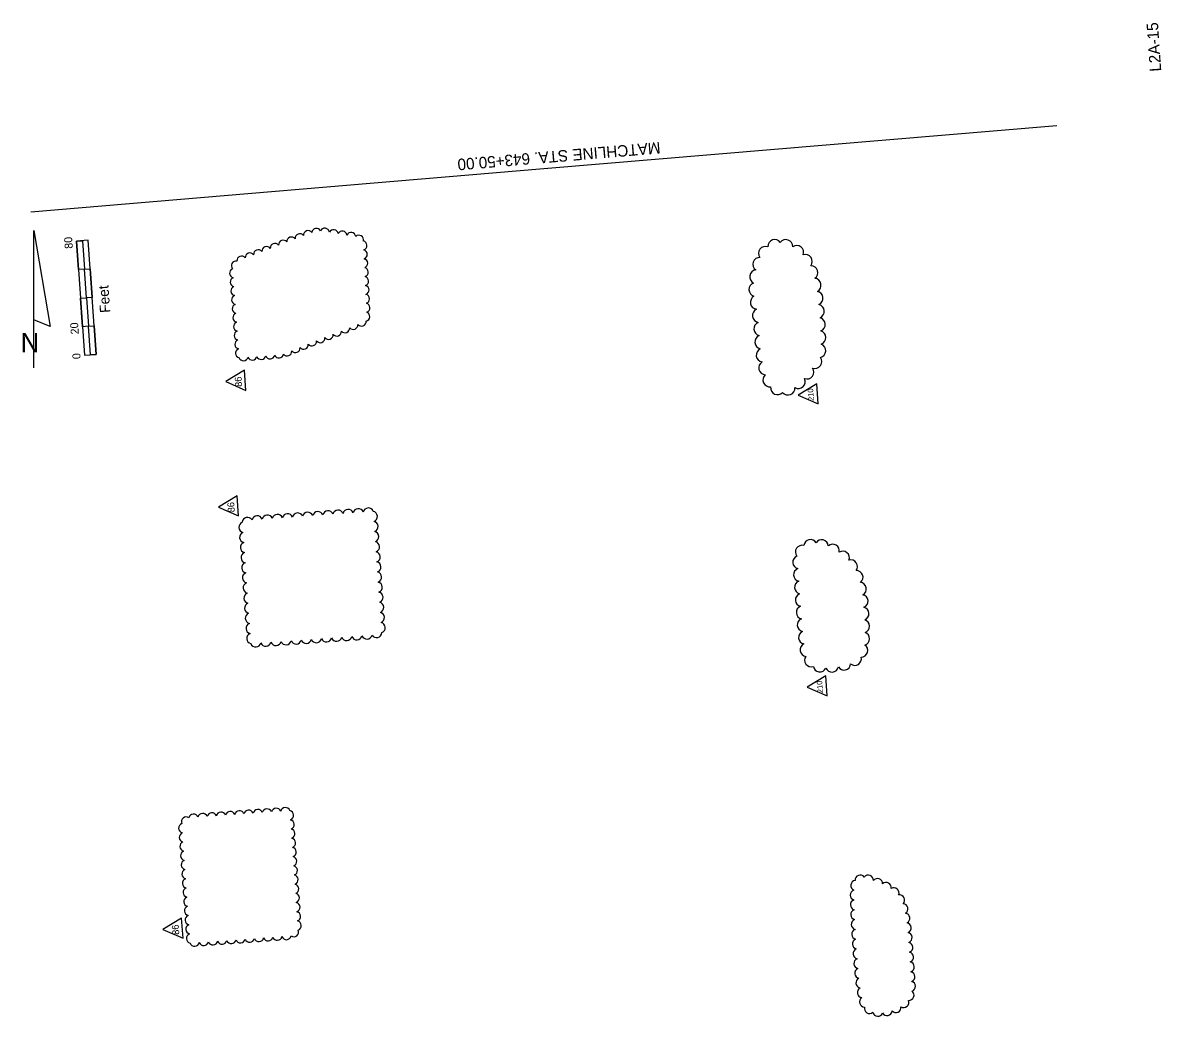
# Model space of a CAD drawing. Extents: x 928662 to 929564, y 639038 to 640295.
# Drawn here: x 928662 to 929458, y 639600 to 640295 of the extents above; entities that cross this region are included whole.
import ezdxf

# ---------------------------------------------------------------- set-up
doc = ezdxf.new("R2010")
doc.units = 0
for name, color, linetype in [('Cloud_dp', 7, 'Continuous'), ('MatchLines_dp', 7, 'Continuous'), ('NorthArw_dp', 7, 'Continuous'), ('Scale_dp', 7, 'Continuous'), ('TextShtNo', 7, 'Continuous')]:
    doc.layers.add(name, color=color, linetype=linetype)

msp = doc.modelspace()

# ---------------------------------------------------------------- linework, layer by layer
at = {"layer": 'Cloud_dp'}
for points in [[(928803.74, 640043.78), (928817.76, 640037.7), (928816.77, 640051.75)], [(929204.11, 640034.36), (929218.13, 640028.28), (929217.14, 640042.33)], [(928798.6, 639956.07), (928812.63, 639949.99), (928811.64, 639964.04)], [(929210.42, 639830.12), (929224.44, 639824.04), (929223.45, 639838.09)], [(928759.76, 639660.72), (928773.79, 639654.64), (928772.8, 639668.69)]]:
    msp.add_lwpolyline(points, close=True, dxfattribs=at)
for centre, radius, start, end in [((928861.31, 640146.07), 3.27, 38.44496, 183.44496), ((928867.11, 640147.7), 3.27, 27.90022, 172.90022), ((928872.92, 640147.77), 3.27, 8.41691, 153.41691), ((928879.07, 640146.78), 3.27, 8.41691, 153.41691), ((928885.22, 640145.8), 3.27, 8.41691, 153.41691), ((928838.04, 640137.16), 3.27, 38.44496, 183.44496), ((928843.86, 640139.39), 3.27, 38.44496, 183.44496), ((928849.67, 640141.62), 3.27, 38.44496, 183.44496), ((928855.49, 640143.84), 3.27, 38.44496, 183.44496), ((928891.37, 640144.81), 3.27, 8.41691, 153.41691), ((928896.78, 640142.85), 3.27, 346.702, 131.702), ((928899.13, 640138.94), 3.27, 290.27845, 75.27845), ((929187.65, 640138.22), 4.85, 36.45605, 181.45605), ((929195.45, 640138.21), 4.85, 358.40857, 143.40857), ((928820.58, 640130.48), 3.27, 38.44496, 183.44496), ((928826.4, 640132.71), 3.27, 38.44496, 183.44496), ((928832.22, 640134.94), 3.27, 38.44496, 183.44496), ((928899.43, 640132.72), 3.27, 290.27845, 75.27845), ((929181.23, 640133.5), 4.85, 71.25472, 216.25472), ((929203.04, 640134.07), 4.85, 339.41877, 124.41877), ((929209.08, 640127.75), 4.85, 322.92208, 107.92208), ((928810.84, 640124.86), 3.27, 78.21602, 223.21602), ((928814.76, 640128.25), 3.27, 38.44496, 183.44496), ((928899.73, 640126.5), 3.27, 290.27845, 75.27845), ((929177.2, 640125.78), 4.85, 88.62539, 233.62539), ((929212.97, 640119.97), 4.85, 305.19249, 90.19249), ((928809.66, 640119.59), 3.27, 111.71689, 256.71689), ((928900.03, 640120.28), 3.27, 290.27845, 75.27845), ((928900.33, 640114.05), 3.27, 290.27845, 75.27845), ((929175.04, 640117.07), 4.85, 98.42028, 243.42028), ((928810.12, 640113.38), 3.27, 111.71689, 256.71689), ((928810.58, 640107.16), 3.27, 111.71689, 256.71689), ((928900.64, 640107.83), 3.27, 290.27845, 75.27845), ((929174.46, 640108.14), 4.85, 109.16671, 254.16671), ((929215.19, 640111.18), 4.85, 298.16543, 83.16543), ((928811.04, 640100.95), 3.27, 111.71689, 256.71689), ((928900.94, 640101.61), 3.27, 290.27845, 75.27845), ((929175.44, 640099.2), 4.85, 118.43265, 263.43265), ((929216.59, 640102.13), 4.85, 294.39112, 79.39112), ((928811.5, 640094.74), 3.27, 111.71689, 256.71689), ((928901.24, 640095.38), 3.27, 290.27845, 75.27845), ((929176.96, 640089.99), 4.85, 115.30895, 260.30895), ((929217.5, 640092.98), 4.85, 292.00794, 77.00794), ((928811.95, 640088.52), 3.27, 111.71689, 256.71689), ((928812.41, 640082.31), 3.27, 111.71689, 256.71689), ((928898.67, 640085.86), 3.27, 219.29844, 4.29844), ((928901.17, 640089.28), 3.27, 283.41856, 68.41856), ((929177.93, 640080.69), 4.85, 111.51956, 256.51956), ((929218.13, 640083.77), 4.85, 290.76114, 75.76114), ((928812.87, 640076.1), 3.27, 111.71689, 256.71689), ((928875.53, 640076.61), 3.27, 219.29844, 4.29844), ((928881.32, 640078.92), 3.27, 219.29844, 4.29844), ((928887.1, 640081.23), 3.27, 219.29844, 4.29844), ((928892.89, 640083.55), 3.27, 219.29844, 4.29844), ((929218.52, 640074.56), 4.85, 289.15603, 74.15603), ((928813.33, 640069.88), 3.27, 111.71689, 256.71689), ((928858.18, 640069.67), 3.27, 219.29844, 4.29844), ((928863.96, 640071.98), 3.27, 219.29844, 4.29844), ((928869.75, 640074.29), 3.27, 219.29844, 4.29844), ((929178.58, 640071.46), 4.85, 111.62555, 256.62555), ((929218.44, 640065.42), 4.86, 284.84092, 69.84092), ((928813.79, 640063.67), 3.27, 111.71689, 256.71689), ((928816.07, 640061.69), 3.27, 201.51956, 346.51956), ((928822.29, 640062.13), 3.27, 201.51956, 346.51956), ((928828.5, 640062.56), 3.27, 201.51956, 346.51956), ((928834.72, 640063), 3.27, 201.51956, 346.51956), ((928840.87, 640063.58), 3.27, 204.25712, 349.25712), ((928846.61, 640065.04), 3.27, 219.29844, 4.29844), ((928852.39, 640067.35), 3.27, 219.29844, 4.29844), ((929179.56, 640062.36), 4.85, 115.59926, 260.59926), ((929181.32, 640053.44), 4.85, 121.70192, 266.70192), ((929210.2, 640050.49), 4.85, 250.40847, 35.40847), ((929215.75, 640057.89), 4.85, 250.82888, 35.82888), ((929184.24, 640044.94), 4.85, 131.22944, 276.22944), ((929204.19, 640043.84), 4.85, 240.39595, 25.39595), ((929189.58, 640039.5), 4.85, 172.73368, 317.73368), ((929196.95, 640039.29), 4.85, 218.89596, 3.89596), ((928825.71, 639946.29), 3.71, 21.51956, 166.51956), ((928832.78, 639946.78), 3.71, 21.51956, 166.51956), ((928839.84, 639947.28), 3.71, 21.51956, 166.51956), ((928846.91, 639947.78), 3.71, 21.51956, 166.51956), ((928853.98, 639948.27), 3.71, 21.51956, 166.51956), ((928861.04, 639948.77), 3.71, 21.51956, 166.51956), ((928868.11, 639949.27), 3.71, 21.51956, 166.51956), ((928875.17, 639949.76), 3.71, 21.51956, 166.51956), ((928882.24, 639950.26), 3.71, 21.51956, 166.51956), ((928889.31, 639950.76), 3.71, 21.51956, 166.51956), ((928896.37, 639951.25), 3.71, 21.51956, 166.51956), ((928903.44, 639951.75), 3.71, 21.51956, 166.51956), ((928906.03, 639949.5), 3.71, 291.51956, 76.51956), ((928816.6, 639941.99), 3.71, 111.51956, 256.51956), ((928818.94, 639945.22), 3.71, 31.48234, 176.48234), ((928906.52, 639942.43), 3.71, 291.51956, 76.51956), ((928817.09, 639934.92), 3.71, 111.51956, 256.51956), ((928907.02, 639935.37), 3.71, 291.51956, 76.51956), ((929212.58, 639928.78), 4.61, 29.64625, 174.64625), ((928817.59, 639927.86), 3.71, 111.51956, 256.51956), ((928907.52, 639928.3), 3.71, 291.51956, 76.51956), ((929206.75, 639924.76), 4.61, 74.42336, 219.42336), ((929220.54, 639928.67), 4.61, 3.80823, 148.80823), ((929228.22, 639925.53), 4.61, 346.72291, 131.72291), ((928818.08, 639920.79), 3.71, 111.51956, 256.51956), ((928908.01, 639921.24), 3.71, 291.51956, 76.51956), ((928908.51, 639914.17), 3.71, 291.51956, 76.51956), ((929204.88, 639917.54), 4.61, 111.51956, 256.51956), ((929235.25, 639920.62), 4.61, 338.37511, 123.37511), ((929240.91, 639914.51), 4.61, 322.33613, 107.33613), ((928818.58, 639913.72), 3.71, 111.51956, 256.51956), ((928819.08, 639906.66), 3.71, 111.51956, 256.51956), ((928909.01, 639907.1), 3.71, 291.51956, 76.51956), ((929205.49, 639908.76), 4.61, 111.51956, 256.51956), ((929244.8, 639907.08), 4.61, 307.85682, 92.85682), ((928819.57, 639899.59), 3.71, 111.51956, 256.51956), ((928909.5, 639900.04), 3.71, 291.51956, 76.51956), ((929206.11, 639899.98), 4.61, 111.51956, 256.51956), ((929247.1, 639898.85), 4.61, 298.46446, 83.46446), ((928820.07, 639892.53), 3.71, 111.51956, 256.51956), ((928910, 639892.97), 3.71, 291.51956, 76.51956), ((929206.73, 639891.2), 4.61, 111.51956, 256.51956), ((929248.3, 639890.29), 4.61, 292.48809, 77.48809), ((928820.57, 639885.46), 3.71, 111.51956, 256.51956), ((928910.49, 639885.91), 3.71, 291.51956, 76.51956), ((929207.36, 639882.42), 4.61, 111.67462, 256.67462), ((929248.93, 639881.56), 4.61, 290.73286, 75.73286), ((928821.06, 639878.39), 3.71, 111.51956, 256.51956), ((928910.99, 639878.84), 3.71, 291.51956, 76.51956), ((929208.05, 639873.66), 4.61, 112.42543, 257.42543), ((928821.56, 639871.33), 3.71, 111.51956, 256.51956), ((928911.49, 639871.77), 3.71, 291.51956, 76.51956), ((929249.32, 639872.8), 4.61, 289.3615, 74.3615), ((928822.06, 639864.26), 3.71, 111.51956, 256.51956), ((928838.78, 639863.01), 3.71, 201.51956, 346.51956), ((928845.84, 639863.5), 3.71, 201.51956, 346.51956), ((928852.91, 639864), 3.71, 201.51956, 346.51956), ((928859.98, 639864.5), 3.71, 201.51956, 346.51956), ((928867.04, 639864.99), 3.71, 201.51956, 346.51956), ((928874.11, 639865.49), 3.71, 201.51956, 346.51956), ((928881.17, 639865.99), 3.71, 201.51956, 346.51956), ((928888.24, 639866.48), 3.71, 201.51956, 346.51956), ((928895.31, 639866.98), 3.71, 201.51956, 346.51956), ((928902.37, 639867.48), 3.71, 201.51956, 346.51956), ((928909.15, 639868.55), 3.71, 211.48234, 356.48234), ((929208.91, 639864.93), 4.61, 113.72906, 258.72906), ((929249.4, 639864.06), 4.61, 286.63121, 71.63121), ((928824.65, 639862.01), 3.71, 201.51956, 346.51956), ((928831.71, 639862.51), 3.71, 201.51956, 346.51956), ((929210.08, 639856.29), 4.62, 116.74711, 261.74711), ((929248.09, 639855.85), 4.61, 270.26997, 55.26997), ((929213.17, 639849.03), 4.61, 144.35853, 289.35853), ((929236.13, 639846.78), 4.61, 210.71872, 355.71872), ((929243.66, 639850), 4.61, 230.55531, 15.55531), ((929219.25, 639845.44), 4.61, 189.46011, 334.46011), ((929227.63, 639845.31), 4.61, 203.84085, 348.84085), ((928793.98, 639739.03), 3.38, 21.51956, 166.51956), ((928800.4, 639739.49), 3.38, 21.51956, 166.51956), ((928806.83, 639739.94), 3.38, 21.51956, 166.51956), ((928813.26, 639740.39), 3.38, 21.51956, 166.51956), ((928819.68, 639740.84), 3.38, 21.51956, 166.51956), ((928826.11, 639741.29), 3.38, 21.51956, 166.51956), ((928832.54, 639741.74), 3.38, 21.51956, 166.51956), ((928838.96, 639742.2), 3.38, 21.51956, 166.51956), ((928845.39, 639742.65), 3.38, 21.51956, 166.51956), ((928847.74, 639740.6), 3.38, 291.51956, 76.51956), ((928774.11, 639731.69), 3.38, 111.51956, 256.51956), ((928776, 639736.09), 3.38, 56.95108, 201.95108), ((928781.12, 639738.13), 3.38, 21.51956, 166.51956), ((928787.55, 639738.58), 3.38, 21.51956, 166.51956), ((928848.2, 639734.18), 3.38, 291.51956, 76.51956), ((928774.56, 639725.26), 3.38, 111.51956, 256.51956), ((928848.65, 639727.75), 3.38, 291.51956, 76.51956), ((928775.01, 639718.83), 3.38, 111.51956, 256.51956), ((928849.1, 639721.32), 3.38, 291.51956, 76.51956), ((928775.46, 639712.41), 3.38, 111.51956, 256.51956), ((928849.55, 639714.9), 3.38, 291.51956, 76.51956), ((928850, 639708.47), 3.38, 291.51956, 76.51956), ((928775.91, 639705.98), 3.38, 111.51956, 256.51956), ((928776.37, 639699.55), 3.38, 111.51956, 256.51956), ((928850.45, 639702.04), 3.38, 291.51956, 76.51956), ((928776.82, 639693.13), 3.38, 111.51956, 256.51956), ((928850.91, 639695.62), 3.38, 291.51956, 76.51956), ((929244.51, 639691.56), 3.6, 101.00121, 246.00121), ((929247.41, 639695.27), 3.59, 37.91777, 182.91777), ((929253.07, 639695.25), 3.59, 356.85595, 141.85595), ((929259.51, 639692.87), 3.59, 357.42093, 142.42093), ((928777.27, 639686.7), 3.38, 111.51956, 256.51956), ((928851.36, 639689.19), 3.38, 291.51956, 76.51956), ((929244.1, 639684.83), 3.59, 107.09663, 252.09663), ((929265.6, 639690.12), 3.59, 349.0536, 134.0536), ((929271, 639686.37), 3.59, 336.44541, 121.44541), ((928777.72, 639680.27), 3.38, 111.51956, 256.51956), ((928851.81, 639682.76), 3.38, 291.51956, 76.51956), ((928852.26, 639676.34), 3.38, 291.51956, 76.51956), ((929244.16, 639678.01), 3.59, 108.9267, 253.9267), ((929274.9, 639681.39), 3.59, 314.78184, 99.78184), ((929277.22, 639675.25), 3.59, 301.60517, 86.60517), ((928778.17, 639673.85), 3.38, 111.51956, 256.51956), ((928852.71, 639669.91), 3.38, 291.51956, 76.51956), ((929244.39, 639671.18), 3.59, 109.91714, 254.91714), ((929278.58, 639668.64), 3.59, 296.63128, 81.63128), ((928778.62, 639667.42), 3.38, 111.51956, 256.51956), ((928779.08, 639660.99), 3.38, 111.51956, 256.51956), ((928853.16, 639663.48), 3.38, 291.51956, 76.51956), ((929244.72, 639664.35), 3.59, 110.56232, 255.56232), ((929279.5, 639661.9), 3.59, 293.86107, 78.86107), ((928779.53, 639654.57), 3.38, 111.51956, 256.51956), ((928826.87, 639655.68), 3.38, 201.51956, 346.51956), ((928833.29, 639656.13), 3.38, 201.51956, 346.51956), ((928839.72, 639656.59), 3.38, 201.51956, 346.51956), ((928846.15, 639657.04), 3.38, 201.51956, 346.51956), ((928851.27, 639659.08), 3.38, 236.95108, 21.95108), ((929245.11, 639657.51), 3.59, 111.02556, 256.02556), ((929280.15, 639655.11), 3.59, 292.05713, 77.05713), ((928781.88, 639652.52), 3.38, 201.51956, 346.51956), ((928788.31, 639652.97), 3.38, 201.51956, 346.51956), ((928794.73, 639653.43), 3.38, 201.51956, 346.51956), ((928801.16, 639653.88), 3.38, 201.51956, 346.51956), ((928807.59, 639654.33), 3.38, 201.51956, 346.51956), ((928814.01, 639654.78), 3.38, 201.51956, 346.51956), ((928820.44, 639655.23), 3.38, 201.51956, 346.51956), ((929245.56, 639650.68), 3.59, 111.39485, 256.39485), ((929246.05, 639643.85), 3.59, 111.87739, 256.87739), ((929280.66, 639648.28), 3.59, 291.51956, 76.51956), ((929246.61, 639637.03), 3.59, 112.52713, 257.52713), ((929281.14, 639641.44), 3.59, 291.51956, 76.51956), ((929247.26, 639630.22), 3.59, 113.42025, 258.42025), ((929281.62, 639634.6), 3.59, 291.51956, 76.51956), ((929282.1, 639627.77), 3.59, 291.51956, 76.51956), ((929248.05, 639623.43), 3.59, 114.76058, 259.76058), ((929282.52, 639620.94), 3.59, 290.40029, 75.40029), ((929249.05, 639616.7), 3.59, 117.11892, 262.11892), ((929281.49, 639614.8), 3.59, 265.64843, 50.64843), ((929250.53, 639610.14), 3.59, 123.37709, 268.37709), ((929277.9, 639609.84), 3.59, 237.46395, 22.46395), ((929253.91, 639605.63), 3.59, 165.30878, 310.30878), ((929259.72, 639603.75), 3.59, 193.86536, 338.86536), ((929266.22, 639604.2), 3.59, 208.98392, 353.98392), ((929272.41, 639606.29), 3.59, 223.32698, 8.32698)]:
    msp.add_arc(centre, radius, start, end, dxfattribs=at)
at = {"layer": 'MatchLines_dp'}
msp.add_lwpolyline([(929384.91, 640222.63), (929026.17, 640192.5), (928667.43, 640162.36)], dxfattribs=at)
at = {"layer": 'NorthArw_dp'}
msp.add_line((928669.37, 640053.44), (928669.37, 640149.44), dxfattribs=at)
msp.add_lwpolyline([(928669.37, 640087.04), (928669.37, 640149.44), (928680.89, 640082.24)], close=True, dxfattribs=at)
at = {"layer": 'Scale_dp'}
for p, q in [((928707.38, 640142.6), (928699.4, 640142.04)), ((928699.4, 640142.04), (928705, 640062.24)), ((928712.98, 640062.8), (928707.38, 640142.6)), ((928705, 640062.24), (928712.98, 640062.8))]:
    msp.add_line(p, q, dxfattribs=at)
for points in [[(928704.79, 640122.37), (928700.8, 640122.09), (928699.4, 640142.04), (928703.39, 640142.32)], [(928710.18, 640102.7), (928706.19, 640102.42), (928704.79, 640122.37), (928708.78, 640122.65)], [(928707.59, 640082.47), (928703.6, 640082.19), (928702.2, 640102.14), (928706.19, 640102.42)], [(928712.98, 640062.8), (928708.99, 640062.52), (928707.59, 640082.47), (928711.58, 640082.75)]]:
    msp.add_lwpolyline(points, close=True, dxfattribs=at)

# ---------------------------------------------------------------- texts
at = {"layer": 'Cloud_dp'}
for s, height, p in [('86', 4.8, (928815.16, 640040.31)), ('210', 3.8, (929215.06, 640030.39)), ('86', 4.8, (928810.03, 639952.6)), ('210', 3.8, (929221.37, 639826.15)), ('86', 4.8, (928771.19, 639657.24))]:
    msp.add_text(s, height=height, rotation=94.01956, dxfattribs=at).set_placement(p)
at = {"layer": 'MatchLines_dp'}
msp.add_text('MATCHLINE STA. 643+50.00', height=8, rotation=184.80152, dxfattribs=at).set_placement((929107.38, 640211.36))
at = {"layer": 'NorthArw_dp'}
msp.add_text('N', height=13.43, dxfattribs=at).set_placement((928660.25, 640064.31))
at = {"layer": 'Scale_dp'}
for s, height, p in [('80', 5.6, (928696.75, 640136.86)), ('Feet', 7.2, (928722.95, 640092.11)), ('20', 5.6, (928700.96, 640077.03)), ('0', 5.6, (928702.17, 640059.71))]:
    msp.add_text(s, height=height, rotation=94.01956, dxfattribs=at).set_placement(p)
at = {"layer": 'TextShtNo'}
msp.add_text('L2A-15', height=8, rotation=94.01956, dxfattribs=at).set_placement((929458.03, 640260.78))

doc.saveas('drawing.dxf')
